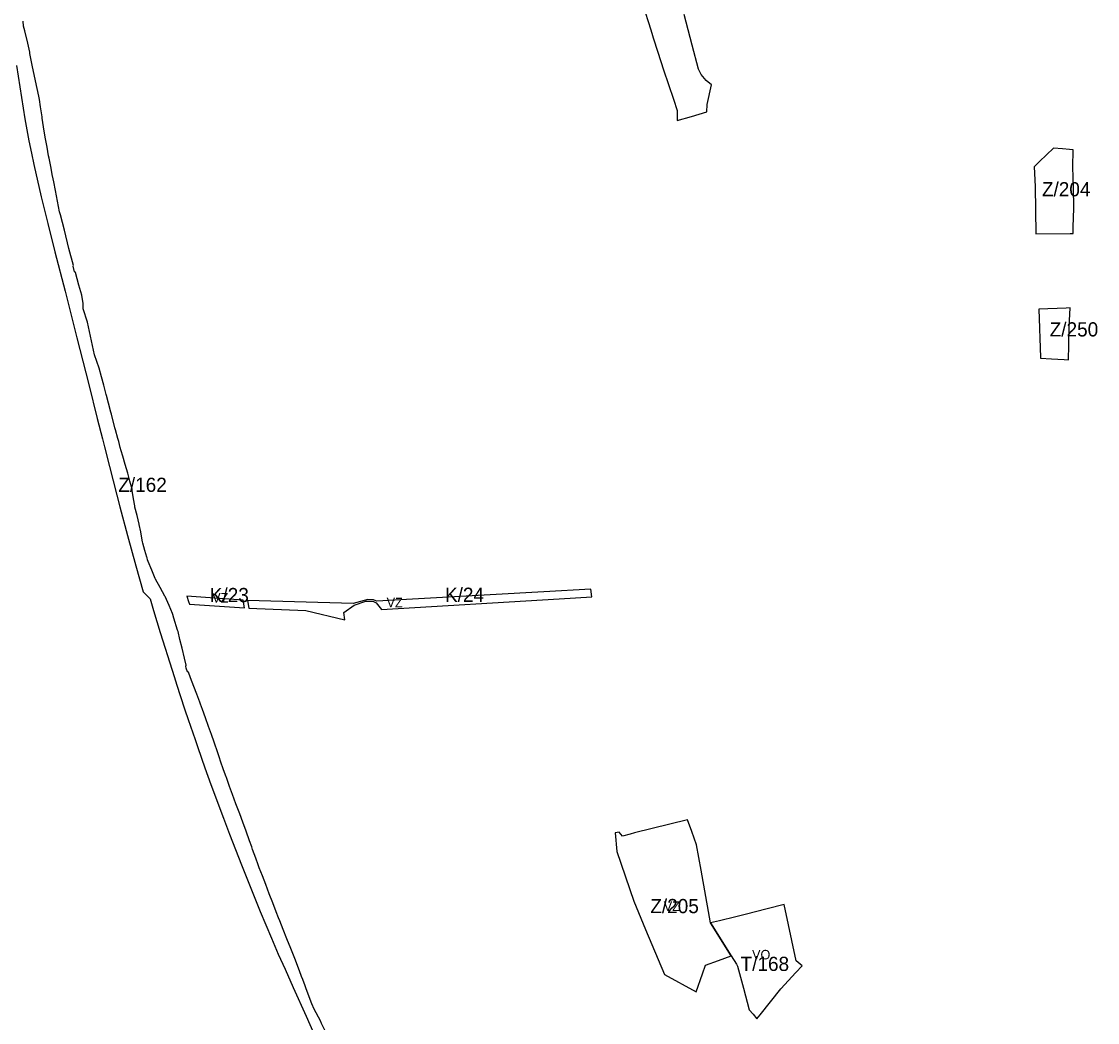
# Model space of a CAD drawing. Extents: x -521939 to -518034, y -1194984 to -1189555.
# Drawn here: x -520833 to -519696, y -1191958 to -1190901 of the extents above; entities that cross this region are included whole.
import ezdxf

# ---------------------------------------------------------------- set-up
doc = ezdxf.new("R2010")
doc.units = 0
for name, color, linetype in [('95420023', 7, 'Continuous'), ('96110023', 7, 'Continuous'), ('96111023', 7, 'Continuous'), ('96202123', 7, 'Continuous'), ('96202223', 7, 'Continuous')]:
    doc.layers.add(name, color=color, linetype=linetype)

msp = doc.modelspace()

# ---------------------------------------------------------------- linework, layer by layer
at = {"layer": '95420023'}
for points in [[(-520174.75, -1190888.89), (-520170.2, -1190903.06)], [(-520830.74, -1190905.71), (-520831.08, -1190900.46)], [(-520170.2, -1190903.06), (-520166.97, -1190913.13)], [(-520124.37, -1190925.82), (-520132.72, -1190893.53)], [(-520829.46, -1190910.89), (-520830.74, -1190905.71)], [(-520826.26, -1190923.93), (-520829.46, -1190910.89)], [(-520166.97, -1190913.13), (-520165.54, -1190917.99)], [(-520824.34, -1190933.44), (-520826.26, -1190923.93)], [(-520165.54, -1190917.99), (-520160.67, -1190933.26)], [(-520117.77, -1190951.37), (-520124.37, -1190925.82)], [(-520824.09, -1190934.71), (-520824.34, -1190933.44)], [(-520822.65, -1190941.82), (-520824.09, -1190934.71)], [(-520160.67, -1190933.26), (-520154.54, -1190951.95)], [(-520838.45, -1190947.47), (-520829.51, -1191003.76)], [(-520814.56, -1190979.91), (-520818.22, -1190963.51), (-520821.62, -1190946.91), (-520821.98, -1190945.15), (-520822.65, -1190941.82)], [(-520154.54, -1190951.95), (-520149.48, -1190967.38)], [(-520114.88, -1190956.87), (-520117.77, -1190951.37)], [(-520109.65, -1190963.19), (-520114.88, -1190956.87)], [(-520149.48, -1190967.38), (-520144.26, -1190983.08)], [(-520104.07, -1190967.71), (-520109.65, -1190963.19)], [(-520108.58, -1190988.66), (-520104.07, -1190967.71)], [(-520812.78, -1190990.94), (-520813.82, -1190983.19), (-520814.56, -1190979.91)], [(-520144.26, -1190983.08), (-520140.38, -1190994.99), (-520140.34, -1190999.22)], [(-520811.15, -1191003.13), (-520811.34, -1191001.73), (-520812.78, -1190990.94)], [(-520109.01, -1190996.4), (-520108.58, -1190988.66)], [(-520829.51, -1191003.76), (-520825.08, -1191027.11)], [(-520807.96, -1191023.01), (-520809.71, -1191012.14), (-520811.15, -1191003.13)], [(-520140.34, -1190999.22), (-520140.24, -1191005.63)], [(-520140.24, -1191005.63), (-520125.17, -1191001.18)], [(-520125.17, -1191001.18), (-520109.01, -1190996.4)], [(-520825.08, -1191027.11), (-520822.58, -1191039.85)], [(-520806.03, -1191033.62), (-520807.96, -1191023.01)], [(-520822.58, -1191039.85), (-520820.01, -1191052.05)], [(-520800.44, -1191062.53), (-520801.76, -1191055.91), (-520803.88, -1191045.24), (-520804.36, -1191042.81), (-520806.03, -1191033.62)], [(-519742.58, -1191034.77), (-519757.4, -1191048.8), (-519763.15, -1191054.45), (-519762.07, -1191075.06), (-519761.34, -1191125.25), (-519725.11, -1191124.72)], [(-519721.98, -1191036.38), (-519725.61, -1191036.1), (-519733.17, -1191035.5), (-519742.58, -1191034.77)], [(-519721.46, -1191075.93), (-519722.16, -1191054.93), (-519721.98, -1191036.38)], [(-520820.01, -1191052.05), (-520812.23, -1191086.24)], [(-520798.81, -1191070.46), (-520799.51, -1191067.05), (-520800.44, -1191062.53)], [(-520796.93, -1191079.59), (-520798.81, -1191070.46)], [(-520812.23, -1191086.24), (-520805.2, -1191114.16)], [(-520791.94, -1191104.99), (-520792.74, -1191102), (-520796.93, -1191079.59)], [(-519721.17, -1191098.04), (-519721.46, -1191075.93)], [(-519721.74, -1191118.03), (-519721.17, -1191098.04)], [(-520783.01, -1191140.89), (-520787.55, -1191121.39), (-520791.94, -1191104.99)], [(-520805.2, -1191114.16), (-520797.61, -1191144.17)], [(-519721.94, -1191124.81), (-519721.74, -1191118.03)], [(-519725.11, -1191124.72), (-519721.94, -1191124.81)], [(-520777.03, -1191165.48), (-520778.32, -1191159.41), (-520777.9, -1191158.6), (-520783.01, -1191140.89)], [(-520797.61, -1191144.17), (-520786.96, -1191185.86)], [(-520775.88, -1191166.14), (-520777.03, -1191165.48)], [(-520772.34, -1191179.58), (-520775.88, -1191166.14)], [(-520786.96, -1191185.86), (-520774.39, -1191235.28)], [(-520767.93, -1191199.01), (-520769.22, -1191190.15), (-520772.34, -1191179.58)], [(-520768, -1191204.35), (-520767.93, -1191199.01)], [(-520759.01, -1191238.19), (-520763.23, -1191218.65), (-520768, -1191204.35)], [(-519729.05, -1191203.74), (-519758.24, -1191204.87)], [(-519758.24, -1191204.87), (-519757.46, -1191224.85)], [(-519725.14, -1191203.59), (-519729.05, -1191203.74)], [(-519726.91, -1191258.21), (-519726.54, -1191242.87), (-519726.09, -1191223.67), (-519725.14, -1191203.59)], [(-519757.46, -1191224.85), (-519757.02, -1191236.26), (-519756.69, -1191244.83)], [(-520774.39, -1191235.28), (-520762.01, -1191284.51)], [(-520755.98, -1191253.01), (-520759.01, -1191238.19)], [(-519756.69, -1191244.83), (-519756.23, -1191256.68)], [(-520750.85, -1191267.23), (-520755.98, -1191253.01)], [(-519756.23, -1191256.68), (-519744.72, -1191257.28), (-519731.19, -1191257.99)], [(-520748.41, -1191276.25), (-520750.85, -1191267.23)], [(-519731.19, -1191257.99), (-519726.91, -1191258.21)], [(-520743.03, -1191296.2), (-520743.4, -1191294.83), (-520746.06, -1191284.98), (-520748.41, -1191276.25)], [(-520762.01, -1191284.51), (-520752.93, -1191320.48)], [(-520741, -1191304.12), (-520743.03, -1191296.2)], [(-520738.56, -1191313.65), (-520741, -1191304.12)], [(-520738.06, -1191315.61), (-520738.56, -1191313.65)], [(-520752.93, -1191320.48), (-520747.53, -1191341.72)], [(-520734.26, -1191330.16), (-520738.06, -1191315.61)], [(-520733.65, -1191332.34), (-520734.26, -1191330.16)], [(-520731.14, -1191341.3), (-520733.65, -1191332.34)], [(-520747.53, -1191341.72), (-520745.31, -1191350.43)], [(-520728.59, -1191350.94), (-520730.21, -1191344.64), (-520731.14, -1191341.3)], [(-520745.31, -1191350.43), (-520740.08, -1191370.95)], [(-520727.71, -1191354.35), (-520728.59, -1191350.94)], [(-520723.44, -1191368.78), (-520726.04, -1191360.01), (-520727.71, -1191354.35)], [(-520740.08, -1191370.95), (-520732.39, -1191401.49)], [(-520722.03, -1191373.58), (-520723.44, -1191368.78)], [(-520720.76, -1191378.14), (-520722.03, -1191373.58)], [(-520718.38, -1191386.7), (-520720.76, -1191378.14)], [(-520716.12, -1191394.83), (-520718.38, -1191386.7)], [(-520732.39, -1191401.49), (-520729.17, -1191413.61)], [(-520715.9, -1191396.27), (-520716.12, -1191394.83)], [(-520714.5, -1191405.34), (-520715.9, -1191396.27)], [(-520729.17, -1191413.61), (-520721.14, -1191444.12)], [(-520707.01, -1191440.35), (-520707.04, -1191440.19), (-520708.5, -1191432.23), (-520708.55, -1191432.06), (-520708.58, -1191431.92), (-520710.82, -1191422.94), (-520713.09, -1191413.86), (-520713.37, -1191412.72), (-520714.5, -1191405.34)], [(-520721.14, -1191444.12), (-520712.23, -1191475.88)], [(-520702.59, -1191459.74), (-520704.85, -1191452.06), (-520705.09, -1191450.73), (-520707.01, -1191440.35)], [(-520700.44, -1191467.02), (-520702.59, -1191459.74)], [(-520699.7, -1191469.55), (-520700.29, -1191467.53), (-520700.44, -1191467.02)], [(-520699.15, -1191471.42), (-520699.7, -1191469.55)], [(-520695.45, -1191480.44), (-520699.15, -1191471.42)], [(-520712.23, -1191475.88), (-520704.46, -1191503.52)], [(-520691.48, -1191490.13), (-520691.77, -1191489.43), (-520695.45, -1191480.44)], [(-520673.22, -1191527.27), (-520673.5, -1191526.37), (-520677.1, -1191518.04), (-520681.26, -1191508.41), (-520681.46, -1191507.94), (-520686.56, -1191498.88), (-520691.48, -1191490.13)], [(-520704.46, -1191503.52), (-520697.13, -1191510.79)], [(-520697.13, -1191510.79), (-520693.46, -1191523.23)], [(-520693.46, -1191523.23), (-520686.61, -1191546.52)], [(-520667.57, -1191545.47), (-520668.09, -1191543.82), (-520672, -1191531.21), (-520673.22, -1191527.27)], [(-520686.61, -1191546.52), (-520681.21, -1191563.06)], [(-520665.57, -1191553.76), (-520667.57, -1191545.47)], [(-520681.21, -1191563.06), (-520678.86, -1191570.86)], [(-520660.82, -1191573.42), (-520663.33, -1191563.05), (-520665.57, -1191553.76)], [(-520678.86, -1191570.86), (-520671.8, -1191593.01)], [(-520659, -1191580.96), (-520660.82, -1191573.42)], [(-520659.53, -1191582.02), (-520659, -1191580.96)], [(-520657.54, -1191587.89), (-520658.88, -1191583.95), (-520659.53, -1191582.02)], [(-520671.8, -1191593.01), (-520668.87, -1191602.22)], [(-520647.71, -1191611.67), (-520650.9, -1191603.35), (-520654.37, -1191594.38), (-520656.67, -1191588.4), (-520657.54, -1191587.89)], [(-520668.87, -1191602.22), (-520665.33, -1191613.04)], [(-520665.33, -1191613.04), (-520660.4, -1191628.12)], [(-520644.52, -1191620), (-520647.71, -1191611.67)], [(-520641.71, -1191627.72), (-520643.73, -1191622.06), (-520644.52, -1191620)], [(-520660.4, -1191628.12), (-520656.86, -1191638.41)], [(-520638.56, -1191636.54), (-520641.71, -1191627.72)], [(-520656.86, -1191638.41), (-520649.42, -1191659.64)], [(-520632.32, -1191654.19), (-520635.33, -1191645.63), (-520638.56, -1191636.54)], [(-520629.49, -1191662.22), (-520632.32, -1191654.19)], [(-520649.42, -1191659.64), (-520646.67, -1191667.99)], [(-520629.16, -1191663.22), (-520629.49, -1191662.22)], [(-520622.73, -1191682.3), (-520623.96, -1191678.84), (-520626.06, -1191672.54), (-520629.16, -1191663.22)], [(-520646.67, -1191667.99), (-520639.25, -1191689.54)], [(-520616.79, -1191698.9), (-520619.43, -1191691.52), (-520622.73, -1191682.3)], [(-520639.25, -1191689.54), (-520632.82, -1191707.09)], [(-520613.42, -1191708.19), (-520614.97, -1191703.91), (-520616.56, -1191699.54), (-520616.79, -1191698.9)], [(-520632.82, -1191707.09), (-520619.58, -1191742.71)], [(-520609.95, -1191717.76), (-520613.08, -1191709.13), (-520613.42, -1191708.19)], [(-520602.48, -1191737.99), (-520606.37, -1191727.43), (-520609.95, -1191717.76)], [(-520619.58, -1191742.71), (-520613.34, -1191759.5)], [(-520599.31, -1191746.66), (-520602.48, -1191737.99)], [(-520129.36, -1191744.38), (-520185.24, -1191758.27)], [(-520124.76, -1191756.84), (-520129.36, -1191744.38)], [(-520585.49, -1191784.87), (-520588.8, -1191775.76), (-520589.8, -1191773.03), (-520592.13, -1191766.51), (-520595.79, -1191756.32), (-520599.31, -1191746.66)], [(-520201.52, -1191757.27), (-520205.83, -1191758.24)], [(-520189.75, -1191759.39), (-520197.9, -1191761.48), (-520201.52, -1191757.27)], [(-520119.69, -1191770.62), (-520124.76, -1191756.84)], [(-520613.34, -1191759.5), (-520600.61, -1191791.87)], [(-520205.83, -1191758.24), (-520203.95, -1191777.85)], [(-520185.24, -1191758.27), (-520189.75, -1191759.39)], [(-520203.95, -1191777.85), (-520185.99, -1191830.46)], [(-520114.94, -1191797.7), (-520119.69, -1191770.62)], [(-520581.71, -1191795.12), (-520582.94, -1191791.88), (-520585.49, -1191784.87)], [(-520600.61, -1191791.87), (-520589.45, -1191820.06)], [(-520574.96, -1191812.85), (-520578.48, -1191803.63), (-520581.71, -1191795.12)], [(-520106.18, -1191847.24), (-520114.94, -1191797.7)], [(-520556.46, -1191860.17), (-520560.11, -1191851.11), (-520561.36, -1191848.01), (-520563.85, -1191841.56), (-520567.46, -1191832.2), (-520571.18, -1191822.61), (-520574.96, -1191812.85)], [(-520589.45, -1191820.06), (-520580.78, -1191841.33)], [(-520185.99, -1191830.46), (-520173.54, -1191860.15)], [(-520580.78, -1191841.33), (-520568.92, -1191869.32)], [(-520105.09, -1191853.21), (-520106.18, -1191847.24)], [(-520083.3, -1191887.96), (-520105.09, -1191853.21)], [(-520568.92, -1191869.32), (-520561.8, -1191886.19)], [(-520552.5, -1191870.05), (-520556.46, -1191860.17)], [(-520548.49, -1191880.24), (-520552.5, -1191870.05)], [(-520173.54, -1191860.15), (-520153.55, -1191907.81)], [(-520537.01, -1191909.76), (-520539.14, -1191903.88), (-520544.3, -1191890.84), (-520548.49, -1191880.24)], [(-520561.8, -1191886.19), (-520554.58, -1191902.23)], [(-520110.14, -1191897.75), (-520096.72, -1191892.86), (-520083.3, -1191887.96)], [(-520554.58, -1191902.23), (-520545.99, -1191921.37)], [(-520113.38, -1191906.91), (-520110.14, -1191897.75)], [(-520507.66, -1191976.43), (-520512.79, -1191965.9), (-520515.96, -1191959.4), (-520517.18, -1191956.82), (-520523.93, -1191944.46), (-520526.29, -1191938.72), (-520532.31, -1191922.75), (-520533.39, -1191919.77), (-520535.87, -1191912.92), (-520537.01, -1191909.76)], [(-520153.55, -1191907.81), (-520120.2, -1191926.19)], [(-520120.2, -1191926.19), (-520113.38, -1191906.91)], [(-520545.99, -1191921.37), (-520532.26, -1191951.92)], [(-520532.26, -1191951.92), (-520524.4, -1191969.39)]]:
    msp.add_lwpolyline(points, dxfattribs=at)
at = {"layer": '96110023'}
for points in [[(-520027.04, -1191833.79), (-520044.99, -1191838.35), (-520068.5, -1191844.29)], [(-520014.4, -1191893.4), (-520027.04, -1191833.79)], [(-520078.22, -1191846.75), (-520095.58, -1191851.22)], [(-520068.5, -1191844.29), (-520078.22, -1191846.75)], [(-520095.58, -1191851.22), (-520105.09, -1191853.21)], [(-520105.09, -1191853.21), (-520083.3, -1191887.96)], [(-520083.3, -1191887.96), (-520077.68, -1191896.92)], [(-520008.2, -1191898.59), (-520014.4, -1191893.4)], [(-520077.68, -1191896.92), (-520076.36, -1191899.02), (-520070.28, -1191922.07), (-520064.19, -1191945.12), (-520060.07, -1191949.85), (-520055.94, -1191954.58)], [(-520030.81, -1191922.99), (-520015.01, -1191905.83), (-520008.2, -1191898.59)], [(-520055.94, -1191954.58), (-520052.53, -1191950.29), (-520030.81, -1191922.99)]]:
    msp.add_lwpolyline(points, dxfattribs=at)
at = {"layer": '96111023'}
for points in [[(-520231.3, -1191500.76), (-520281.01, -1191503.56), (-520457.48, -1191513.5), (-520461.23, -1191511.82), (-520467.01, -1191511.47), (-520482.44, -1191515.66), (-520594.1, -1191512.73)], [(-520230.44, -1191508.92), (-520231.3, -1191500.76)], [(-520658.4, -1191508.21), (-520656.53, -1191513.73), (-520655.62, -1191516.43)], [(-520598.71, -1191512.42), (-520658.4, -1191508.21)], [(-520655.62, -1191516.43), (-520597.37, -1191520.53)], [(-520597.37, -1191520.53), (-520598.71, -1191512.42)], [(-520594.1, -1191512.73), (-520592.74, -1191520.81)], [(-520491.32, -1191533.14), (-520492.29, -1191525.29), (-520481.62, -1191517.42), (-520469.32, -1191513.47), (-520461.73, -1191513.47), (-520458.29, -1191515), (-520452.73, -1191522.22)], [(-520452.73, -1191522.22), (-520264.87, -1191510.98), (-520230.44, -1191508.92)], [(-520592.74, -1191520.81), (-520532.56, -1191523.11)], [(-520532.56, -1191523.11), (-520491.32, -1191533.14)]]:
    msp.add_lwpolyline(points, dxfattribs=at)
at = {"layer": '96202123'}
for points in [[(-520027.04, -1191833.79), (-520044.99, -1191838.35), (-520068.5, -1191844.29)], [(-520014.4, -1191893.4), (-520027.04, -1191833.79)], [(-520078.22, -1191846.75), (-520095.58, -1191851.22)], [(-520068.5, -1191844.29), (-520078.22, -1191846.75)], [(-520095.58, -1191851.22), (-520105.09, -1191853.21)], [(-520105.09, -1191853.21), (-520083.3, -1191887.96)], [(-520083.3, -1191887.96), (-520077.68, -1191896.92)], [(-520008.2, -1191898.59), (-520014.4, -1191893.4)], [(-520077.68, -1191896.92), (-520076.36, -1191899.02), (-520070.28, -1191922.07), (-520064.19, -1191945.12), (-520060.07, -1191949.85), (-520055.94, -1191954.58)], [(-520030.81, -1191922.99), (-520015.01, -1191905.83), (-520008.2, -1191898.59)], [(-520055.94, -1191954.58), (-520052.53, -1191950.29), (-520030.81, -1191922.99)]]:
    msp.add_lwpolyline(points, dxfattribs=at)
at = {"layer": '96202223'}
for points in [[(-520231.3, -1191500.76), (-520281.01, -1191503.56), (-520457.48, -1191513.5), (-520461.23, -1191511.82), (-520467.01, -1191511.47), (-520482.44, -1191515.66), (-520594.1, -1191512.73)], [(-520230.44, -1191508.92), (-520231.3, -1191500.76)], [(-520658.4, -1191508.21), (-520656.53, -1191513.73), (-520655.62, -1191516.43)], [(-520598.71, -1191512.42), (-520658.4, -1191508.21)], [(-520655.62, -1191516.43), (-520597.37, -1191520.53)], [(-520597.37, -1191520.53), (-520598.71, -1191512.42)], [(-520594.1, -1191512.73), (-520592.74, -1191520.81)], [(-520491.32, -1191533.14), (-520492.29, -1191525.29), (-520481.62, -1191517.42), (-520469.32, -1191513.47), (-520461.73, -1191513.47), (-520458.29, -1191515), (-520452.73, -1191522.22)], [(-520452.73, -1191522.22), (-520264.87, -1191510.98), (-520230.44, -1191508.92)], [(-520592.74, -1191520.81), (-520532.56, -1191523.11)], [(-520532.56, -1191523.11), (-520491.32, -1191533.14)], [(-520129.36, -1191744.38), (-520185.24, -1191758.27)], [(-520124.76, -1191756.84), (-520129.36, -1191744.38)], [(-520201.52, -1191757.27), (-520205.83, -1191758.24)], [(-520189.75, -1191759.39), (-520197.9, -1191761.48), (-520201.52, -1191757.27)], [(-520119.69, -1191770.62), (-520124.76, -1191756.84)], [(-520205.83, -1191758.24), (-520203.95, -1191777.85)], [(-520185.24, -1191758.27), (-520189.75, -1191759.39)], [(-520203.95, -1191777.85), (-520185.99, -1191830.46)], [(-520114.94, -1191797.7), (-520119.69, -1191770.62)], [(-520106.18, -1191847.24), (-520114.94, -1191797.7)], [(-520185.99, -1191830.46), (-520173.54, -1191860.15)], [(-520105.09, -1191853.21), (-520106.18, -1191847.24)], [(-520083.3, -1191887.96), (-520105.09, -1191853.21)], [(-520173.54, -1191860.15), (-520153.55, -1191907.81)], [(-520110.14, -1191897.75), (-520096.72, -1191892.86), (-520083.3, -1191887.96)], [(-520113.38, -1191906.91), (-520110.14, -1191897.75)], [(-520153.55, -1191907.81), (-520120.2, -1191926.19)], [(-520120.2, -1191926.19), (-520113.38, -1191906.91)]]:
    msp.add_lwpolyline(points, dxfattribs=at)

# ---------------------------------------------------------------- texts
at = {"layer": '95420023'}
for s, p in [('Z/204', (-519754.83, -1191085.62)), ('Z/250', (-519746.63, -1191233.68)), ('Z/162', (-520730.77, -1191397.89)), ('Z/205', (-520168.62, -1191842.97))]:
    msp.add_text(s, height=15, rotation=0, dxfattribs=at).set_placement(p)
at = {"layer": '96110023'}
msp.add_text('T/168', height=15, rotation=360, dxfattribs=at).set_placement((-520073.24, -1191904.04))
at = {"layer": '96111023'}
for s, rotation, p in [('K/23', 0, (-520634.06, -1191514.39)), ('K/24', 360, (-520385.57, -1191514.09))]:
    msp.add_text(s, height=15, rotation=rotation, dxfattribs=at).set_placement(p)
at = {"layer": '96202123'}
msp.add_text('VO', height=10, rotation=360, dxfattribs=at).set_placement((-520061.09, -1191891.81))
at = {"layer": '96202223'}
for p in [(-520631.53, -1191514.76), (-520447.22, -1191519.77), (-520154.42, -1191840.61)]:
    msp.add_text('VZ', height=10, rotation=0, dxfattribs=at).set_placement(p)

doc.saveas('drawing.dxf')
